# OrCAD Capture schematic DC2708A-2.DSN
size Custom; title: HIGH EFFICIENCY 4 PHASE 120A; rev: 2; company: TM
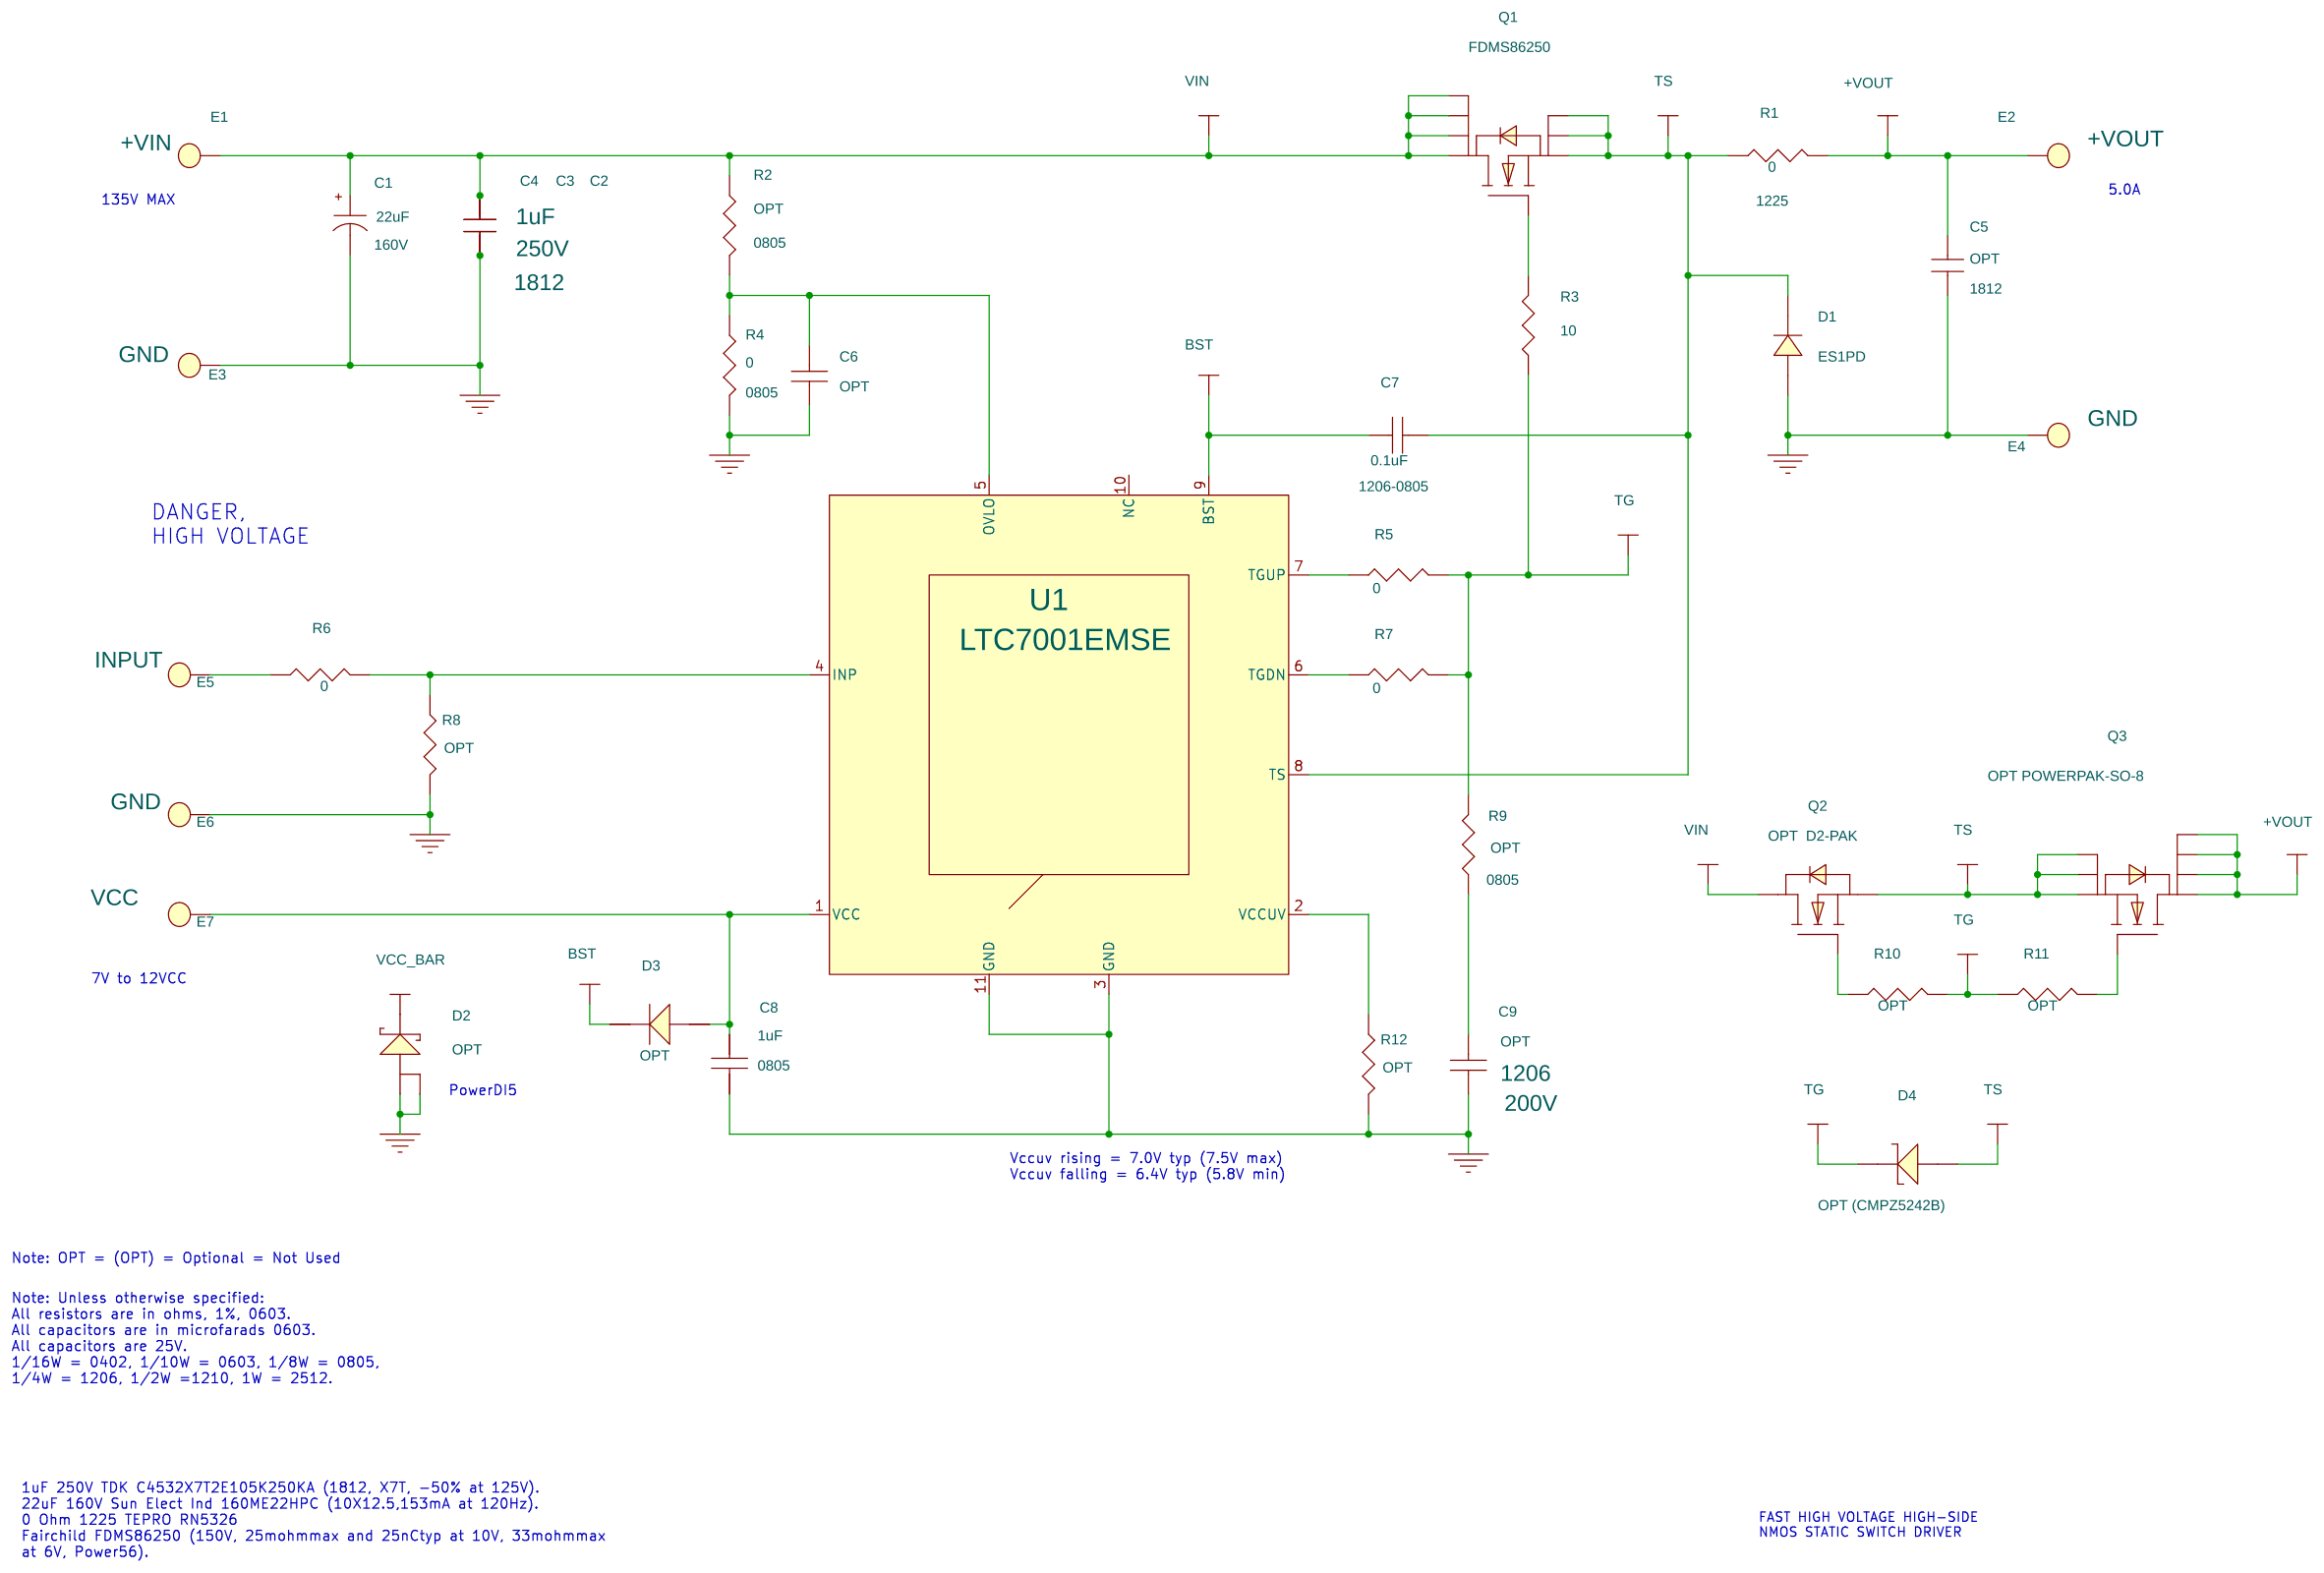
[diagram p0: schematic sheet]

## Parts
C1  22uF  [CAP-TH-10D]
C2  1uF  [1812]
C3  1uF  [1812]
C4  1uF  [1812]
C5  OPT  [1812]
C6  OPT  [0603]
C7  0.1uF  [1206-0805]
C8  1uF  [0805]
C9  OPT  [1206]
D1  ES1PD  [DO-220AA]
D2  OPT  [POWERDI5]
D3  OPT  [SOT23]
D4  OPT (CMPZ5242B)  [SOT23]
E1  TURRET  [PAD150-094]
E2  TURRET  [PAD150-094]
E3  TURRET  [PAD150-094]
E4  TURRET  [PAD150-094]
E5  TURRET  [PAD150-094]
E6  TURRET  [PAD150-094]
E7  TURRET  [PAD150-094]
Q1  FDMS86250  [POWERPAK-SO-8]
Q2  OPT  D2-PAK  [D2-PAK]
Q3  OPT POWERPAK-SO-8  [POWERPAK-SO-8]
R1  0  [1225]
R2  OPT  [0805]
R3  10  [0603]
R4  0  [0805]
R5  0  [0603]
R6  0  [0603]
R7  0  [0603]
R8  OPT  [0603]
R9  OPT  [0805]
R10  OPT  [0603]
R11  OPT  [0603]
R12  OPT  [0603]
U1  LTC7001EMSE  [MSE10]

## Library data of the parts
C1 = CAP-HVH-10X10.5: 1ST PART FIELD: 160V; 5TH PART FIELD: 10X20
C2-C4 = CAP1210: 1ST PART FIELD: 250V; 2ND PART FIELD: 20%, 1210; 3RD PART FIELD: X7R; 4TH PART FIELD: TDK; 5TH PART FIELD: 1210; 7TH PART FIELD: CAP.
C5 = CAP1210: 1ST PART FIELD: 100V; 2ND PART FIELD: 20%, 1210; 3RD PART FIELD: X7R; 4TH PART FIELD: TDK; 5TH PART FIELD: 1210; 7TH PART FIELD: CAP.
C6 = 12061C104KAT2A_0: 1ST PART FIELD: 25V; 2ND PART FIELD: 10%, 0603; 3RD PART FIELD: NPO; 4TH PART FIELD: AVX; 5TH PART FIELD: 06033A471KAT2A; 7TH PART FIELD: CAP.
C7 = 12061C104KAT2A_0: 1ST PART FIELD: 25V; 2ND PART FIELD: 10%, 0805; 3RD PART FIELD: X7R; 4TH PART FIELD: AVX; 5TH PART FIELD: 0805; 7TH PART FIELD: CAP.
C8 = TMK316BJ105KL: 1ST PART FIELD: 16V; 2ND PART FIELD: 10%, 0805; 3RD PART FIELD: X7R; 4TH PART FIELD: TAIYO TUDEN; 7TH PART FIELD: CAP.
C9 = 12061C104KAT2A_0: 1ST PART FIELD: 200V; 2ND PART FIELD: 10%, 0206; 3RD PART FIELD: X7R; 4TH PART FIELD: AVX; 7TH PART FIELD: CAP.
D1 = DIODE_8
D2 = DIODE-PDS3100_0
D3 = CMPSH1-4_14
D4 = CMPSH1-4_16
E1 = TURRET_2501-2: 7TH PART FIELD: HOLE,; 9TH PART FIELD: +VIN
E2 = TURRET_2501-2: 7TH PART FIELD: HOLE,; 9TH PART FIELD: +VOUT
E3 E4 = TURRET_2501-2: 7TH PART FIELD: HOLE,; 9TH PART FIELD: GND
E5 = TURRET_2501-2: 9TH PART FIELD: INPUT
E6 = TURRET_2501-2: 9TH PART FIELD: GND
E7 = TURRET_2501-2: 9TH PART FIELD: VCC
Q1 Q3 = SI7456DP: 1ST PART FIELD: 150V; 2ND PART FIELD: POWERPAK SO-8; 3RD PART FIELD: N-CHANNEL; 5TH PART FIELD: Si7450DP; 7TH PART FIELD: FET; opt: *
Q2 = SI7456DP_3: 1ST PART FIELD: 150V; 2ND PART FIELD: POWERPAK SO-8; 3RD PART FIELD: N-CHANNEL; 5TH PART FIELD: Si7450DP; 7TH PART FIELD: FET; opt: *
R1 = AAC-0805: 1ST PART FIELD: 1/2W; 2ND PART FIELD: 1%, 1210; 5TH PART FIELD: 1210; 7TH PART FIELD: RES.
R2 R4 R9 = AAC-0805: 2ND PART FIELD: 1%, 0805; 7TH PART FIELD: RES.
R3 R5-R8 R10-R12 = AAC-0805: 1ST PART FIELD: 1/16W; 2ND PART FIELD: 1%, 0603; 5TH PART FIELD: CR16-xxxxFM; 7TH PART FIELD: RES.
U1 = LTC7001EMSE_0: 3RD PART FIELD: ANALOG; 4TH PART FIELD: LINEAR TECH.; 5TH PART FIELD: LTC7000EMS16E; 7TH PART FIELD: I.C.

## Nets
GND: C1.2 C2.2 C3.2 C4.2 C5.2 C6.2 C8.2 C9.2 D1.2(K) D2.2 D2.3 E3.1 E4.1 E6.1 R4.1 R8.2 R12.2 U1.3(GND) U1.11(GND)
VIN: C1.1 C2.1 C3.1 C4.1 D2.1 E1.1 Q1.5 Q1.6 Q1.7 Q1.8 Q2.D R2.2
+VOUT: C5.1 E2.1 Q3.5 Q3.6 Q3.7 Q3.8 R1.1
BST: C7.2 D3.3(K) U1.9(BST)
TG: D4.3(K) R3.1 R5.2 R7.2 R9.1 R10.2 R11.1
TS: C7.1 D1.1(A) D4.1(A) Q1.1 Q1.2 Q1.3 Q2.S Q3.1 Q3.2 Q3.3 R1.2 U1.8(TS)
N19086535: C6.1 R2.1 R4.2 U1.5(OVLO)
N19086551: C9.1 R9.2
N19086705: Q1.4 R3.2
N19086942: R5.1 U1.7(TGUP)
N19087011: R7.1 U1.6(TGDN)
N19087249: R6.2 R8.1 U1.4(INP)
N19087358: E5.1 R6.1
N19087366: R12.1 U1.2(VCCUV)
N19092294: Q3.4 R11.2
N19096314: C8.1 D3.1(A) E7.1 U1.1(VCC)
N19109237: Q2.G R10.1

Not connected (* = marked no-connect by the designer): U1 10(NC)

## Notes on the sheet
- 5.0A
- 135V MAX
- DANGER,
  HIGH VOLTAGE
- 7V to 12VCC
- PowerDI5
- Vccuv rising = 7.0V typ (7.5V max)
  Vccuv falling = 6.4V typ (5.8V min)
- Note: OPT = (OPT) = Optional = Not Used
- Note: Unless otherwise specified:
  All resistors are in ohms, 1%, 0603.
  All capacitors are in microfarads 0603.
  All capacitors are 25V.
  1/16W = 0402, 1/10W = 0603, 1/8W = 0805,
  1/4W = 1206, 1/2W =1210, 1W = 2512.
- 1uF 250V TDK C4532X7T2E105K250KA (1812, X7T, -50% at 125V).
  22uF 160V Sun Elect Ind 160ME22HPC (10X12.5,153mA at 120Hz).
  0 Ohm 1225 TEPRO RN5326
  Fairchild FDMS86250 (150V, 25mohmmax and 25nCtyp at 10V, 33mohmmax
  at 6V, Power56).
- FAST HIGH VOLTAGE HIGH-SIDE
  NMOS STATIC SWITCH DRIVER
